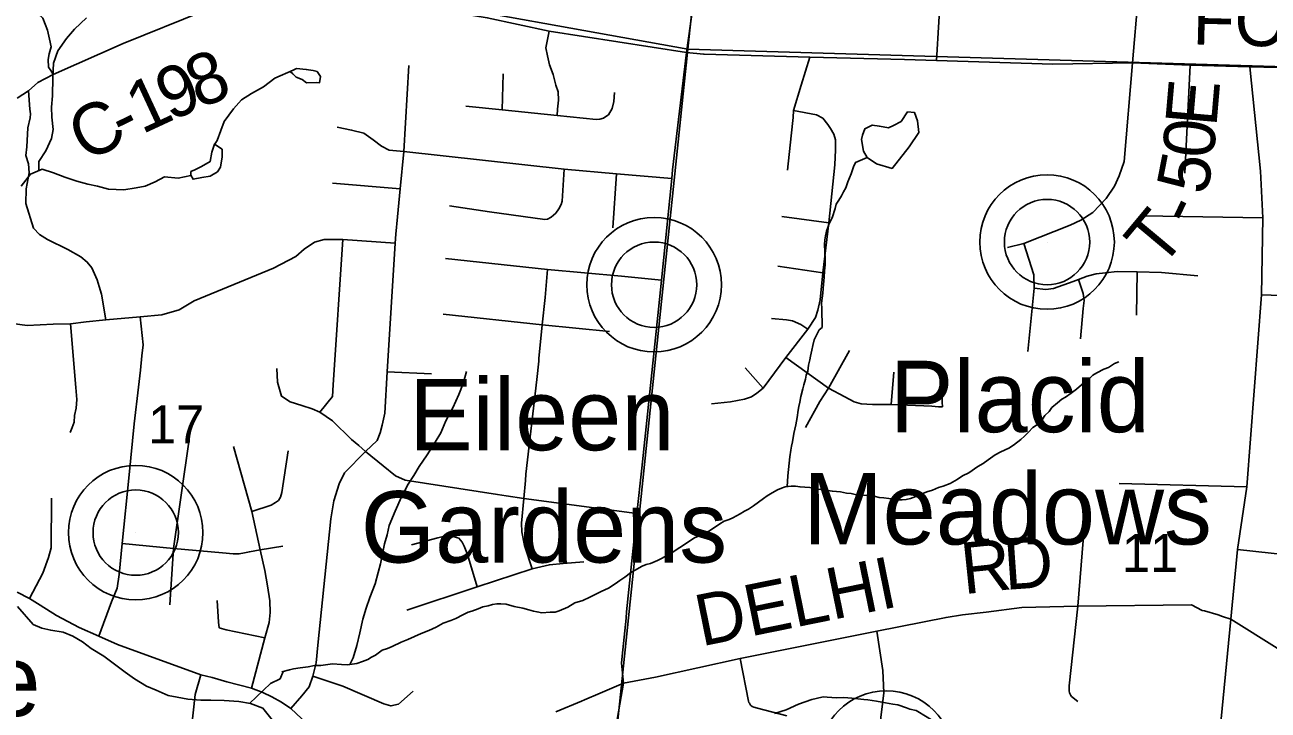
# Model space of a CAD drawing. Extents: x 0 to 43.4, y -8.1 to 22.
# Drawn here: x 6.917 to 8.292, y 15.497 to 16.255 of the extents above; entities that cross this region are included whole.
import ezdxf

# ---------------------------------------------------------------- set-up
doc = ezdxf.new("R2010")
doc.units = 0
for name, color, linetype in [('GM_X_Corporation', 7, 'Continuous'), ('GM_X_County_Road', 7, 'Continuous'), ('GM_X_County_Road_Text', 7, 'Continuous'), ('GM_X_Minor_Lake', 7, 'Continuous'), ('GM_X_Minor_River', 7, 'Continuous'), ('GM_X_Section_Text', 7, 'Continuous'), ('GM_X_Township_Road', 7, 'Continuous'), ('GM_X_Township_Road_Text', 7, 'Continuous'), ('GM_X_Unincorporated', 7, 'Continuous'), ('GM_X_Unincorporated_Location', 7, 'Continuous'), ('GM_X_Unincorporated_Text', 7, 'Continuous')]:
    doc.layers.add(name, color=color, linetype=linetype)

msp = doc.modelspace()

# ---------------------------------------------------------------- linework, layer by layer
at = {"layer": 'GM_X_Corporation'}
for points in [[(7.7575, 17.2431), (7.6501, 16.228), (6.6267, 16.4119), (6.7271, 17.3517)], [(7.7575, 17.2431), (8.7485, 17.1931), (8.6363, 16.199), (7.6501, 16.228)], [(7.6501, 16.228), (7.5438, 15.2065), (6.5194, 15.3962), (6.6267, 16.4119)], [(8.6363, 16.199), (8.5356, 15.1762), (7.5438, 15.2065), (7.6501, 16.228)]]:
    msp.add_lwpolyline(points, close=True, dxfattribs=at)
at = {"layer": 'GM_X_County_Road'}
for p, q in [((8.1491, 16.294), (8.1419, 16.2128)), ((7.5696, 15.4718), (7.579, 15.5267))]:
    msp.add_line(p, q, dxfattribs=at)
for points in [[(7.5825, 15.6055), (7.5876, 15.6551), (7.5938, 15.7142), (7.5992, 15.7645), (7.6179, 15.9405), (7.6211, 15.9725), (7.6324, 16.0848), (7.6334, 16.0946), (7.6488, 16.2242), (7.6616, 16.3173), (7.6639, 16.369), (7.6701, 16.4333), (7.6877, 16.6246), (7.6932, 16.6628)], [(6.9083, 16.1739), (6.921, 16.1817), (6.9314, 16.1911), (6.9481, 16.2), (7.0257, 16.2343), (7.1152, 16.2703), (7.1761, 16.2963), (7.1774, 16.2967), (7.1787, 16.2967), (7.1812, 16.2964), (7.1889, 16.2949), (7.2573, 16.2866), (7.3578, 16.2741), (7.4283, 16.2627), (7.4967, 16.248), (7.6488, 16.2242), (7.6674, 16.2224), (7.6684, 16.2223)], [(7.6684, 16.2223), (7.7851, 16.2192), (7.8897, 16.2164), (7.9253, 16.2153), (8.0538, 16.2112), (8.1419, 16.2128)], [(8.1419, 16.2128), (8.2056, 16.2102), (8.2716, 16.2083)], [(8.2507, 15.5974), (8.258, 15.6744), (8.2685, 15.744), (8.2845, 15.9562), (8.2862, 16.0414), (8.2836, 16.093), (8.2716, 16.2083)], [(8.2716, 16.2083), (8.427, 16.2046), (8.4709, 16.2033), (8.4984, 16.2028), (8.639, 16.2005)], [(8.2845, 15.9562), (8.4847, 15.9494), (8.6082, 15.9452), (8.7294, 15.9293), (8.7612, 15.9251)], [(8.258, 15.6744), (8.3155, 15.6682), (8.37, 15.6624), (8.4552, 15.6595), (8.5777, 15.6455), (8.693, 15.6342), (8.8525, 15.6132), (8.88, 15.6102), (8.9, 15.6093)], [(6.9083, 15.6272), (6.9219, 15.6203), (6.934, 15.6131), (6.9518, 15.6014), (6.9771, 15.5883), (6.9986, 15.5785), (7.0192, 15.5696), (7.1116, 15.536), (7.1241, 15.5331), (7.1402, 15.5282), (7.1676, 15.521), (7.1803, 15.5164), (7.1902, 15.5114), (7.2006, 15.5057), (7.2112, 15.4986), (7.2347, 15.4766)], [(7.536, 15.5082), (7.5532, 15.5155), (7.579, 15.5267), (7.6143, 15.5333), (7.7079, 15.5539), (7.8591, 15.5841), (7.9358, 15.5995), (7.9541, 15.6024), (7.98, 15.6051), (8.0195, 15.6102), (8.0814, 15.6119), (8.2071, 15.6132), (8.219, 15.607), (8.2217, 15.6066), (8.2369, 15.6022), (8.2415, 15.6006)], [(7.5775, 15.5567), (7.5818, 15.5985), (7.5825, 15.6055)], [(8.2129, 15.2407), (8.2301, 15.3849), (8.2507, 15.5974)], [(8.2415, 15.6006), (8.2507, 15.5974), (8.302, 15.5653)], [(7.579, 15.5267), (7.5767, 15.5489), (7.5775, 15.5567)], [(7.7598, 15.4907), (7.7271, 15.4992), (7.723, 15.5001), (7.7213, 15.501), (7.7196, 15.5024), (7.7182, 15.5044), (7.7175, 15.5054), (7.7171, 15.5067), (7.7079, 15.5539)], [(7.5042, 15.4951), (7.5327, 15.5069), (7.536, 15.5082)]]:
    msp.add_lwpolyline(points, dxfattribs=at)
at = {"layer": 'GM_X_Minor_Lake'}
msp.add_line((7.1006, 16.0928), (7.1003, 16.0886), dxfattribs=at)
for points in [[(7.1933, 16.1959), (7.2137, 16.2049), (7.2175, 16.2067), (7.2281, 16.2056), (7.2357, 16.2043), (7.2402, 16.2034), (7.2438, 16.1976), (7.2429, 16.1908), (7.2395, 16.1909), (7.2285, 16.1908), (7.2236, 16.1943), (7.2169, 16.1968), (7.2132, 16.2007)], [(7.2132, 16.2007), (7.2102, 16.2034)], [(7.8587, 16.1012), (7.8761, 16.096), (7.8949, 16.1198), (7.9055, 16.1359), (7.9043, 16.1485), (7.9008, 16.158), (7.8932, 16.1586), (7.8861, 16.1478), (7.8776, 16.1434), (7.8723, 16.1409), (7.8621, 16.1426), (7.8541, 16.144), (7.8461, 16.14), (7.8432, 16.1328)], [(7.8433, 16.133), (7.8424, 16.1279), (7.8443, 16.115), (7.8487, 16.108)], [(7.1003, 16.0886), (7.103, 16.084), (7.1126, 16.086), (7.1217, 16.0873), (7.1298, 16.0924), (7.1334, 16.0976), (7.1352, 16.109), (7.135, 16.1173), (7.1268, 16.1229), (7.1236, 16.1142), (7.1218, 16.1036), (7.1121, 16.0982), (7.1048, 16.0946)], [(7.8587, 16.1012), (7.8487, 16.108)], [(7.1048, 16.0946), (7.1006, 16.0928)]]:
    msp.add_lwpolyline(points, dxfattribs=at)
at = {"layer": 'GM_X_Minor_River'}
for points in [[(6.9324, 16.0937), (6.9322, 16.1037), (6.94, 16.1156), (6.9465, 16.1291), (6.9482, 16.139), (6.9467, 16.1527), (6.9462, 16.1637), (6.9473, 16.1762), (6.9478, 16.1967), (6.9486, 16.2123), (6.9535, 16.2262), (6.9629, 16.2396), (6.9719, 16.25), (6.9852, 16.2626)], [(7.1267, 16.1226), (7.1296, 16.127), (7.1337, 16.1379), (7.1374, 16.148), (7.1476, 16.1618), (7.1566, 16.1718), (7.1674, 16.1791), (7.1809, 16.1864), (7.1933, 16.1959)], [(7.7986, 15.9202), (7.7984, 15.941), (7.7982, 15.9471), (7.7987, 15.9525), (7.7996, 15.9581), (7.7997, 15.9631), (7.8002, 15.9677), (7.8008, 15.9756), (7.8014, 15.9829), (7.802, 15.9893), (7.8021, 15.9958), (7.8016, 16.0042), (7.8014, 16.0118), (7.8016, 16.0171), (7.8024, 16.0213), (7.8037, 16.0266), (7.805, 16.0307), (7.8066, 16.0353), (7.8098, 16.0413), (7.8132, 16.0518), (7.8144, 16.0564), (7.8172, 16.0609), (7.82, 16.0658), (7.8224, 16.0703), (7.8248, 16.0744), (7.8273, 16.0812), (7.8309, 16.0902), (7.8334, 16.0977), (7.8358, 16.1026), (7.8487, 16.108)], [(6.9129, 16.0764), (6.9231, 16.0898), (6.9361, 16.0952), (6.9485, 16.0911), (6.9613, 16.0862), (6.9745, 16.0821), (6.9866, 16.0788), (6.9971, 16.0766), (7.0096, 16.0732), (7.0262, 16.0724), (7.04, 16.0744), (7.0499, 16.0764), (7.061, 16.0811), (7.0714, 16.0869), (7.0864, 16.0852), (7.1005, 16.0882)], [(7.7601, 15.744), (7.7607, 15.7562), (7.7631, 15.7771), (7.7641, 15.7843), (7.765, 15.7889), (7.7659, 15.7938), (7.7676, 15.8029), (7.7685, 15.8078), (7.7698, 15.8123), (7.7703, 15.8165), (7.7711, 15.8207), (7.7721, 15.8287), (7.773, 15.8328), (7.7739, 15.8374), (7.7752, 15.8438), (7.7773, 15.8521), (7.7786, 15.8567), (7.7803, 15.8631), (7.7812, 15.8673), (7.7828, 15.8718), (7.7837, 15.8786), (7.785, 15.8843), (7.7859, 15.8884), (7.7872, 15.8949), (7.7885, 15.9002), (7.7898, 15.9066), (7.7926, 15.9115), (7.7954, 15.9175), (7.7986, 15.9202)], [(7.2763, 15.5473), (7.2799, 15.5546), (7.2841, 15.5685), (7.2874, 15.5825), (7.2908, 15.5973), (7.2945, 15.6097), (7.2985, 15.6214), (7.3045, 15.6365), (7.3078, 15.649), (7.3103, 15.6588), (7.3146, 15.6807), (7.3175, 15.6909), (7.32, 15.7011), (7.3264, 15.717), (7.3336, 15.7328), (7.3407, 15.7467), (7.347, 15.7564), (7.3529, 15.7662), (7.3619, 15.7793), (7.3706, 15.7931), (7.3769, 15.8036), (7.3825, 15.8168), (7.3904, 15.8311), (7.3968, 15.8458), (7.4016, 15.8582), (7.4053, 15.8714)], [(7.8619, 15.7321), (7.8668, 15.7316), (7.8725, 15.731), (7.8775, 15.7305), (7.8828, 15.7296), (7.8873, 15.7295), (7.8915, 15.7297), (7.8965, 15.7311), (7.9023, 15.7332), (7.9065, 15.735), (7.9146, 15.7382), (7.9207, 15.7403), (7.9276, 15.7432), (7.9326, 15.7446), (7.9403, 15.7474), (7.948, 15.7521), (7.9538, 15.7562), (7.9608, 15.7594), (7.9708, 15.7664), (7.977, 15.7696), (7.9825, 15.7736), (7.9902, 15.7791), (7.9964, 15.7824), (8.0052, 15.7867), (8.0103, 15.79), (8.0184, 15.7963), (8.0227, 15.7999), (8.027, 15.8044), (8.0317, 15.8096), (8.0371, 15.8129), (8.0426, 15.8188), (8.045, 15.8229), (8.0497, 15.827), (8.0529, 15.8315), (8.0591, 15.8366), (8.0638, 15.8407), (8.068, 15.8432), (8.0742, 15.8476), (8.08, 15.8517), (8.0882, 15.8587), (8.0933, 15.8627), (8.0983, 15.8672), (8.1026, 15.8701), (8.1103, 15.8741), (8.1153, 15.8758), (8.1222, 15.8802), (8.1268, 15.882)], [(7.2011, 15.5391), (7.2095, 15.5416), (7.2141, 15.5426), (7.2213, 15.5435), (7.2301, 15.5448), (7.2374, 15.5461), (7.2442, 15.5463), (7.2572, 15.5482), (7.2671, 15.5472), (7.2739, 15.547), (7.2789, 15.5476), (7.2842, 15.5486), (7.2904, 15.5507), (7.2961, 15.5529), (7.3004, 15.5554), (7.3046, 15.5576), (7.312, 15.5631), (7.3181, 15.5652), (7.3231, 15.5673), (7.3332, 15.572), (7.3405, 15.5749), (7.3551, 15.5817), (7.3636, 15.5849), (7.372, 15.5885), (7.3797, 15.5932), (7.3882, 15.596), (7.3936, 15.5981), (7.4013, 15.6021), (7.4071, 15.6054), (7.4113, 15.6064), (7.4182, 15.6089), (7.4236, 15.611), (7.4293, 15.6124), (7.4343, 15.6138), (7.4389, 15.6144), (7.4435, 15.6146), (7.4491, 15.6141), (7.4582, 15.6116), (7.4677, 15.6098), (7.4745, 15.6077), (7.4794, 15.6064), (7.4835, 15.6055), (7.4888, 15.6046), (7.498, 15.6051), (7.5033, 15.6054), (7.5079, 15.6067), (7.5175, 15.6107), (7.5252, 15.6154), (7.5341, 15.6182), (7.5418, 15.6218), (7.5468, 15.6243), (7.5545, 15.6279), (7.5626, 15.6319), (7.5699, 15.6366), (7.575, 15.6403), (7.5804, 15.644), (7.5866, 15.6487), (7.5939, 15.6527), (7.5997, 15.656), (7.604, 15.6578), (7.6089, 15.6592), (7.6166, 15.6624), (7.6209, 15.6645), (7.6278, 15.6681), (7.6329, 15.6711), (7.6414, 15.6769), (7.6464, 15.6802), (7.6511, 15.6835), (7.6576, 15.6875), (7.6696, 15.6925), (7.6754, 15.6958), (7.6854, 15.7031), (7.6905, 15.706), (7.6958, 15.7078), (7.7001, 15.7096), (7.7082, 15.7139), (7.7128, 15.7168), (7.7171, 15.719), (7.7229, 15.723), (7.7337, 15.7311), (7.738, 15.734), (7.7434, 15.7373), (7.7492, 15.7406), (7.7538, 15.7423), (7.758, 15.7437), (7.7645, 15.7447), (7.7691, 15.7446), (7.7744, 15.7437), (7.7797, 15.7435), (7.785, 15.743), (7.7896, 15.7421), (7.7998, 15.7407), (7.81, 15.7389), (7.8191, 15.7382), (7.8255, 15.7369), (7.8309, 15.7364), (7.8369, 15.7351), (7.8411, 15.7349), (7.8513, 15.7339), (7.8562, 15.7334), (7.8619, 15.7321)], [(6.9089, 15.6114), (6.926, 15.5915)], [(7.1905, 15.4861), (7.1802, 15.4989), (7.1663, 15.5042), (7.1534, 15.5064), (7.1375, 15.5076), (7.1227, 15.5079), (7.1117, 15.5078), (7.0973, 15.509), (7.0852, 15.5112), (7.0754, 15.5129), (7.0623, 15.5189), (7.0514, 15.5234), (7.0383, 15.5313), (7.0279, 15.5388), (7.0044, 15.5565), (6.9902, 15.5652), (6.9805, 15.5723), (6.9701, 15.5786), (6.9592, 15.5831), (6.9456, 15.5853), (6.9357, 15.5874), (6.926, 15.5915)], [(7.2026, 15.5396), (7.1992, 15.5315), (7.1885, 15.5264), (7.1655, 15.5043)], [(7.7459, 15.4931), (7.759, 15.4973), (7.7724, 15.5034), (7.7874, 15.5087), (7.792, 15.5097), (7.8, 15.5114), (7.8042, 15.5113), (7.8145, 15.5106), (7.8228, 15.5107), (7.8316, 15.5101), (7.8448, 15.5086), (7.8494, 15.5081), (7.8588, 15.5067), (7.8649, 15.5057), (7.877, 15.5035), (7.8823, 15.5026), (7.8921, 15.4993)], [(7.8921, 15.4993), (7.8959, 15.498), (7.9027, 15.4963), (7.915, 15.4891), (7.9195, 15.4863), (7.9233, 15.4839), (7.9338, 15.4787), (7.9387, 15.477), (7.947, 15.4749), (7.9575, 15.4712), (7.9673, 15.4675), (7.9775, 15.4638), (7.9805, 15.4629), (7.9854, 15.462), (7.9884, 15.4615)]]:
    msp.add_lwpolyline(points, dxfattribs=at)
at = {"layer": 'GM_X_Township_Road'}
for p, q in [((7.4449, 16.1609), (7.4459, 16.2005)), ((8.2056, 16.2102), (8.2, 16.0909)), ((7.5711, 16.0901), (7.5672, 16.0303)), ((7.2571, 16.0796), (7.332, 16.0735)), ((7.8061, 16.0357), (7.7542, 16.0428)), ((8.2862, 16.0414), (8.1535, 16.0437)), ((7.4948, 15.9843), (7.4924, 15.9532)), ((7.7995, 15.9807), (7.7497, 15.9879)), ((8.1472, 15.9815), (8.1465, 15.9338)), ((7.4892, 15.9232), (7.3797, 15.935)), ((7.4892, 15.9232), (7.5636, 15.9157)), ((7.8058, 15.8529), (7.829, 15.8948)), ((7.3178, 15.8711), (7.3666, 15.8689)), ((7.7336, 15.853), (7.7137, 15.8753)), ((7.8752, 15.8351), (7.8782, 15.8707)), ((8.1273, 15.7474), (8.2685, 15.744)), ((8.0814, 15.6119), (8.0889, 15.7027))]:
    msp.add_line(p, q, dxfattribs=at)
for points in [[(7.9253, 16.2153), (7.9303, 16.3012), (7.9386, 16.4436)], [(6.8522, 16.2841), (6.8581, 16.2825), (6.8632, 16.2814), (6.8724, 16.2806), (6.8921, 16.277), (6.9079, 16.2744), (6.9195, 16.2722), (6.9257, 16.2702), (6.9318, 16.2672), (6.9367, 16.2621), (6.9419, 16.249), (6.9443, 16.2391), (6.9459, 16.2305), (6.9439, 16.2229), (6.9426, 16.2165), (6.9432, 16.2082), (6.9456, 16.2044), (6.9481, 16.2)], [(7.4967, 16.248), (7.4931, 16.2294), (7.4948, 16.2206), (7.4973, 16.2105), (7.5011, 16.1998), (7.5041, 16.1883), (7.5069, 16.1806), (7.5071, 16.1717), (7.5061, 16.1617), (7.5055, 16.1547)], [(7.7851, 16.2192), (7.7755, 16.1881), (7.7672, 16.1602), (7.7665, 16.1525), (7.7646, 16.132), (7.7604, 16.0942)], [(8.0038, 16.0084), (8.0217, 16.0129), (8.0731, 16.0333), (8.0848, 16.0388), (8.0981, 16.0473), (8.1127, 16.0626), (8.1219, 16.0763), (8.1273, 16.0879), (8.1328, 16.1038), (8.1419, 16.2128)], [(7.3274, 16.0234), (7.3291, 16.0424), (7.332, 16.0735), (7.336, 16.1148), (7.3417, 16.2098)], [(6.921, 16.1817), (6.9224, 16.1615), (6.923, 16.1566), (6.9226, 16.152), (6.9201, 16.141), (6.9191, 16.1198), (6.918, 16.1105), (6.9209, 16.1013), (6.9216, 16.0913), (6.9182, 16.0736), (6.918, 16.0571), (6.9266, 16.0301), (6.933, 16.023), (6.9419, 16.0173), (6.9643, 16.0062), (6.9789, 15.9984), (6.986, 15.9924), (6.991, 15.986), (6.997, 15.9728), (6.9992, 15.9654)], [(7.4048, 16.1648), (7.4449, 16.1609), (7.5055, 16.1547), (7.5487, 16.1501), (7.5529, 16.1507), (7.5568, 16.1518), (7.5596, 16.1533), (7.5625, 16.1555), (7.5666, 16.1625), (7.5685, 16.1702), (7.5692, 16.1799)], [(7.7672, 16.1602), (7.7925, 16.1552), (7.7996, 16.1516), (7.8051, 16.1447), (7.8081, 16.1401), (7.8115, 16.134), (7.8136, 16.1276), (7.8136, 16.1165), (7.8127, 16.1001), (7.8061, 16.0357), (7.7995, 15.9807), (7.7964, 15.9506), (7.7939, 15.9393), (7.7914, 15.9313), (7.783, 15.9182), (7.7585, 15.8868), (7.7336, 15.853), (7.7264, 15.8475), (7.7205, 15.8433), (7.713, 15.8407), (7.6973, 15.8377), (7.6763, 15.8356)], [(7.6324, 16.0848), (7.5711, 16.0901), (7.5135, 16.0952), (7.336, 16.1148), (7.3198, 16.1162), (7.3114, 16.1206), (7.3023, 16.1276), (7.292, 16.1351), (7.2783, 16.1384), (7.2623, 16.1418)], [(7.3867, 16.0545), (7.4308, 16.0479), (7.4921, 16.0396), (7.495, 16.0399), (7.4989, 16.0421), (7.504, 16.0465), (7.5074, 16.0513), (7.5099, 16.056), (7.5111, 16.0599), (7.5135, 16.0952)], [(7.2112, 15.4986), (7.2233, 15.5125), (7.2312, 15.5228), (7.2354, 15.5346), (7.239, 15.5492), (7.2408, 15.5687), (7.2555, 15.7084), (7.2587, 15.7283), (7.2644, 15.7472), (7.2705, 15.7593), (7.2936, 15.7831), (7.3064, 15.7952), (7.31, 15.8034), (7.3121, 15.8121), (7.3152, 15.8253), (7.3178, 15.8711), (7.3264, 16.0134), (7.3274, 16.0234)], [(7.3264, 16.0134), (7.2685, 16.0173), (7.2479, 16.0176), (7.2372, 16.0144), (7.2258, 16.0066), (7.2166, 15.9988), (7.192, 15.9856), (7.123, 15.9575), (7.1043, 15.9497), (7.0876, 15.9397), (7.0685, 15.9342), (7.0445, 15.9319), (7.0063, 15.9287), (6.9846, 15.9262), (6.9675, 15.9242), (6.9484, 15.9237), (6.9193, 15.9223), (6.8495, 15.9319)], [(7.2685, 16.0173), (7.258, 15.8568), (7.257, 15.8436), (7.2431, 15.8265)], [(8.0217, 16.0129), (8.0329, 15.9782), (8.0333, 15.9635), (8.0261, 15.8936)], [(7.382, 15.9963), (7.4948, 15.9843), (7.5769, 15.977), (7.6211, 15.9725)], [(8.0333, 15.9635), (8.0462, 15.9622), (8.0545, 15.9633), (8.0764, 15.9709), (8.0824, 15.9731), (8.092, 15.977), (8.1017, 15.9793), (8.1121, 15.9805), (8.125, 15.9819), (8.1472, 15.9815), (8.1742, 15.9811), (8.2143, 15.9771)], [(6.9992, 15.9654), (7.0016, 15.9571), (7.0063, 15.9287)], [(8.0824, 15.9731), (8.0873, 15.9577), (8.0887, 15.9501), (8.0873, 15.941), (8.0845, 15.9077)], [(7.4924, 15.9532), (7.4892, 15.9232), (7.4855, 15.8857), (7.4852, 15.8827)], [(6.9669, 15.8041), (6.9694, 15.8095), (6.9716, 15.8155), (6.9719, 15.8226), (6.9737, 15.8308), (6.9744, 15.8404), (6.9734, 15.8536), (6.9675, 15.9242)], [(6.9986, 15.5785), (7.0129, 15.6168), (7.0189, 15.6317), (7.0214, 15.647), (7.0246, 15.6812), (7.0321, 15.7573), (7.0378, 15.8136), (7.0427, 15.8541), (7.0447, 15.8728), (7.0463, 15.8888), (7.0477, 15.9011), (7.0467, 15.9114), (7.0445, 15.9319)], [(7.783, 15.9182), (7.7753, 15.9233), (7.7659, 15.9275), (7.7593, 15.9286), (7.7426, 15.9302)], [(7.4852, 15.8827), (7.4832, 15.8627), (7.4711, 15.7577), (7.4705, 15.7507)], [(7.7585, 15.8868), (7.8058, 15.8529), (7.8238, 15.8434), (7.8343, 15.8379), (7.842, 15.8356), (7.8545, 15.8351), (7.8752, 15.8351), (7.9199, 15.8332), (7.9273, 15.8323), (7.9317, 15.8324), (7.9316, 15.8374), (7.9321, 15.8617), (7.9339, 15.8703)], [(7.1956, 15.8749), (7.1964, 15.8597), (7.2006, 15.8441), (7.2103, 15.8379), (7.2232, 15.8337), (7.2345, 15.8301), (7.2431, 15.8265), (7.257, 15.8169), (7.278, 15.7963), (7.2862, 15.7894)], [(7.7803, 15.8095), (7.7963, 15.8384), (7.8058, 15.8529)], [(7.0987, 15.7962), (7.0812, 15.6758), (7.0773, 15.6135)], [(7.1676, 15.521), (7.1824, 15.5769), (7.1872, 15.5938), (7.1883, 15.6047), (7.1877, 15.6178), (7.1851, 15.6344), (7.1822, 15.6513), (7.1773, 15.6741), (7.168, 15.7166), (7.1477, 15.7885)], [(7.2862, 15.7894), (7.2936, 15.7831), (7.3132, 15.7671), (7.3267, 15.7561), (7.3374, 15.7511), (7.4395, 15.7355), (7.4493, 15.734)], [(7.168, 15.7166), (7.1894, 15.7235), (7.1943, 15.7264), (7.1974, 15.7289), (7.1996, 15.7324), (7.201, 15.7375), (7.208, 15.7835)], [(7.4705, 15.7507), (7.4687, 15.7308), (7.4663, 15.7036), (7.4664, 15.6941), (7.4694, 15.6788), (7.478, 15.6531)], [(6.9219, 15.6203), (6.9369, 15.6484), (6.943, 15.6656), (6.946, 15.6763), (6.9464, 15.7314)], [(7.4493, 15.734), (7.4687, 15.7308), (7.5938, 15.7142)], [(7.417, 15.6332), (7.4066, 15.6691), (7.4027, 15.6784), (7.4004, 15.6825), (7.3969, 15.6869), (7.3919, 15.6885), (7.384, 15.6902), (7.3735, 15.6875), (7.3445, 15.6798)], [(7.0246, 15.6812), (7.0812, 15.6758), (7.1354, 15.6707), (7.1472, 15.6698), (7.1536, 15.6696), (7.158, 15.6705), (7.1653, 15.6721), (7.1773, 15.6741), (7.2023, 15.6782)], [(7.3395, 15.6073), (7.417, 15.6332), (7.478, 15.6531), (7.4971, 15.6577), (7.5122, 15.6589), (7.535, 15.6608)], [(7.1297, 15.618), (7.1311, 15.5942), (7.132, 15.588), (7.1397, 15.5855), (7.1824, 15.5769)], [(8.0814, 15.6119), (8.072, 15.5238), (8.072, 15.5181), (8.0723, 15.5161), (8.0729, 15.5144), (8.0737, 15.513), (8.0747, 15.512), (8.0817, 15.5065)], [(7.8591, 15.5841), (7.866, 15.5407), (7.8669, 15.516), (7.8621, 15.4767), (7.8573, 15.4611), (7.8553, 15.4561)], [(7.1116, 15.536), (7.1054, 15.5141), (7.0972, 15.4397), (7.1057, 15.417), (7.1114, 15.4091), (7.116, 15.4029), (7.1269, 15.396), (7.137, 15.3899), (7.1733, 15.3814), (7.2043, 15.3762)], [(7.2354, 15.5346), (7.2685, 15.5234), (7.3139, 15.5038), (7.3217, 15.5015), (7.3301, 15.5033), (7.3463, 15.518)]]:
    msp.add_lwpolyline(points, dxfattribs=at)
at = {"layer": 'GM_X_Unincorporated'}
for centre, radius in [((8.0475, 16.0146), 0.0744), ((8.0475, 16.0146), 0.0472), ((7.6129, 15.9674), 0.0744), ((7.6129, 15.9674), 0.0472), ((7.0395, 15.6932), 0.0744), ((7.0395, 15.6932), 0.0472), ((7.8697, 15.4439), 0.0744)]:
    msp.add_circle(centre, radius, dxfattribs=at)
at = {"layer": 'GM_X_Unincorporated_Location'}
for p, q in [((8.0475, 16.0146), (8.0475, 16.0146)), ((7.6129, 15.9674), (7.6129, 15.9674)), ((7.0395, 15.6932), (7.0395, 15.6932))]:
    msp.add_line(p, q, dxfattribs=at)

# ---------------------------------------------------------------- texts
at = {"layer": 'GM_X_County_Road_Text'}
for s, height, rotation, p in [('FOLEY', 0.05682, 358.5154, (8.2079, 16.2333)), ('9', 0.0568, 23.2637, (7.0776, 16.1479)), ('8', 0.0568, 22.1995, (7.1095, 16.1616)), ('1', 0.0568, 24.8624, (7.0462, 16.1334)), ('C', 0.0568, 26.9032, (6.9841, 16.1022)), ('-', 0.0568, 26.1732, (7.0256, 16.1232)), ('R', 0.0568, 6, (7.9553, 15.625)), ('D', 0.0568, 4.0176, (8.0012, 15.6298)), ('DELHI', 0.05682, 11.4874, (7.6651, 15.5672))]:
    msp.add_text(s, height=height, rotation=rotation, dxfattribs=at).set_placement(p)
at = {"layer": 'GM_X_Section_Text'}
for s, p in [('17', (7.0531, 15.792)), ('11', (8.1302, 15.6498))]:
    msp.add_text(s, height=0.04186, rotation=0, dxfattribs=at).set_placement(p)
at = {"layer": 'GM_X_Township_Road_Text'}
for s, rotation, p in [('E', 85.0858, (8.2347, 16.1412)), ('0', 84.6987, (8.2314, 16.106)), ('5', 78.8571, (8.2238, 16.0654)), ('T', 50.1426, (8.1733, 15.9839)), ('-', 64.6372, (8.209, 16.0297))]:
    msp.add_text(s, height=0.0568, rotation=rotation, dxfattribs=at).set_placement(p)
at = {"layer": 'GM_X_Unincorporated_Text'}
for s, p in [('Placid', (7.8735, 15.8043)), ('Eileen', (7.3418, 15.7843)), ('Meadows', (7.7777, 15.6801)), ('Gardens', (7.2885, 15.6601)), ('Sunaire', (6.5702, 15.4901))]:
    msp.add_text(s, height=0.07898, rotation=0, dxfattribs=at).set_placement(p)

doc.saveas('drawing.dxf')
